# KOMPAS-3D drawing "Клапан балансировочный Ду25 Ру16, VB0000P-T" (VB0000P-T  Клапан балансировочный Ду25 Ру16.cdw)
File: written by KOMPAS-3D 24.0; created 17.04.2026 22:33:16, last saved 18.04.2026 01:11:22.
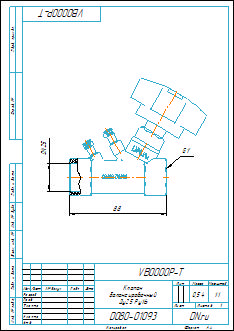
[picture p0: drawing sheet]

Document properties: Автор: tyuri; Форматы листов документа: A4; Полное имя файла: VB0000P-T  Клапан балансировочный Ду25 Ру16.m3d; Масса: 0.54; Наименование: Клапан балансировочный Ду25 Ру16; Количество листов документа: 1; Примечание: D080-01093

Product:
- Body: Тело 2  | qty 1
    Масса: 1.063236
- Part/product: Клапан балансировочный Ду25 Ру16  | designation VB0000P-T
    Масса: 0.54
    Раздел спецификации: Прочие изделия
    Примечание: D080-01093

Views: Вид 1, Местный разрез 1, Справа
Referenced files in D:\Аутсорс\VB0000P-T Клапан балансировочный статический DN.ru\DN25\: VB0000P-T  Клапан балансировочный статический Ду25 Ру16.m3d
Referenced files in E:\Работа\Зайцев\АУТСОРС\Диман\Балансировка\VB0000P-T Клапан балансировочный DN.ru Ду15-50 Ру16\DN25\: VB0000P-T  Клапан балансировочный Ду25 Ру16.m3d
Referenced files in D:\Аутсорс\VB0000P-T Клапан балансировочный статический DN.ru\DN20\: VB0000P-T  Клапан балансировочный статический Ду15 Ру16.cdw
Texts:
  VB0000P-T
  Клапан
  балансировочный
  Ду25 Ру16
  Клапан балансировочный Ду25 Ру16
  VB0000P-T Клапан балансировочный Ду25 Ру16
Dimensions and other numbers on the sheet: 0; 3; 2; 4; 25; 88; 1:1; 1; 0,54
